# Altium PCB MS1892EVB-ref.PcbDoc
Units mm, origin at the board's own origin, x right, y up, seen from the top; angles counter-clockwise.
Board outline 71.73 x 36.12 mm, 2 copper layers (Top Layer, Bottom Layer); 57 components, 56 nets, 213 pads, 111 vias.
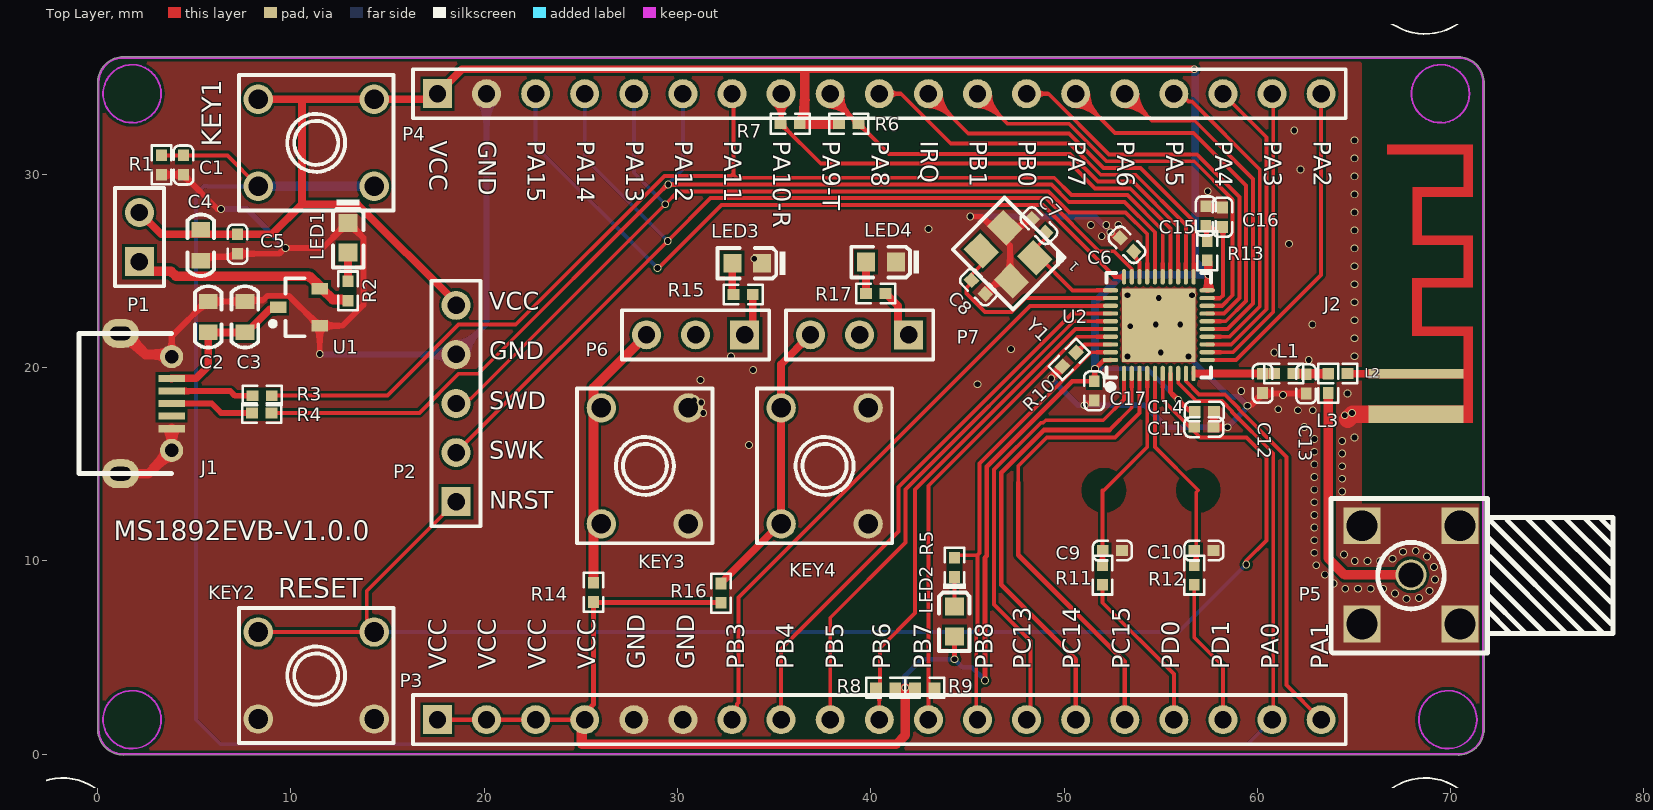
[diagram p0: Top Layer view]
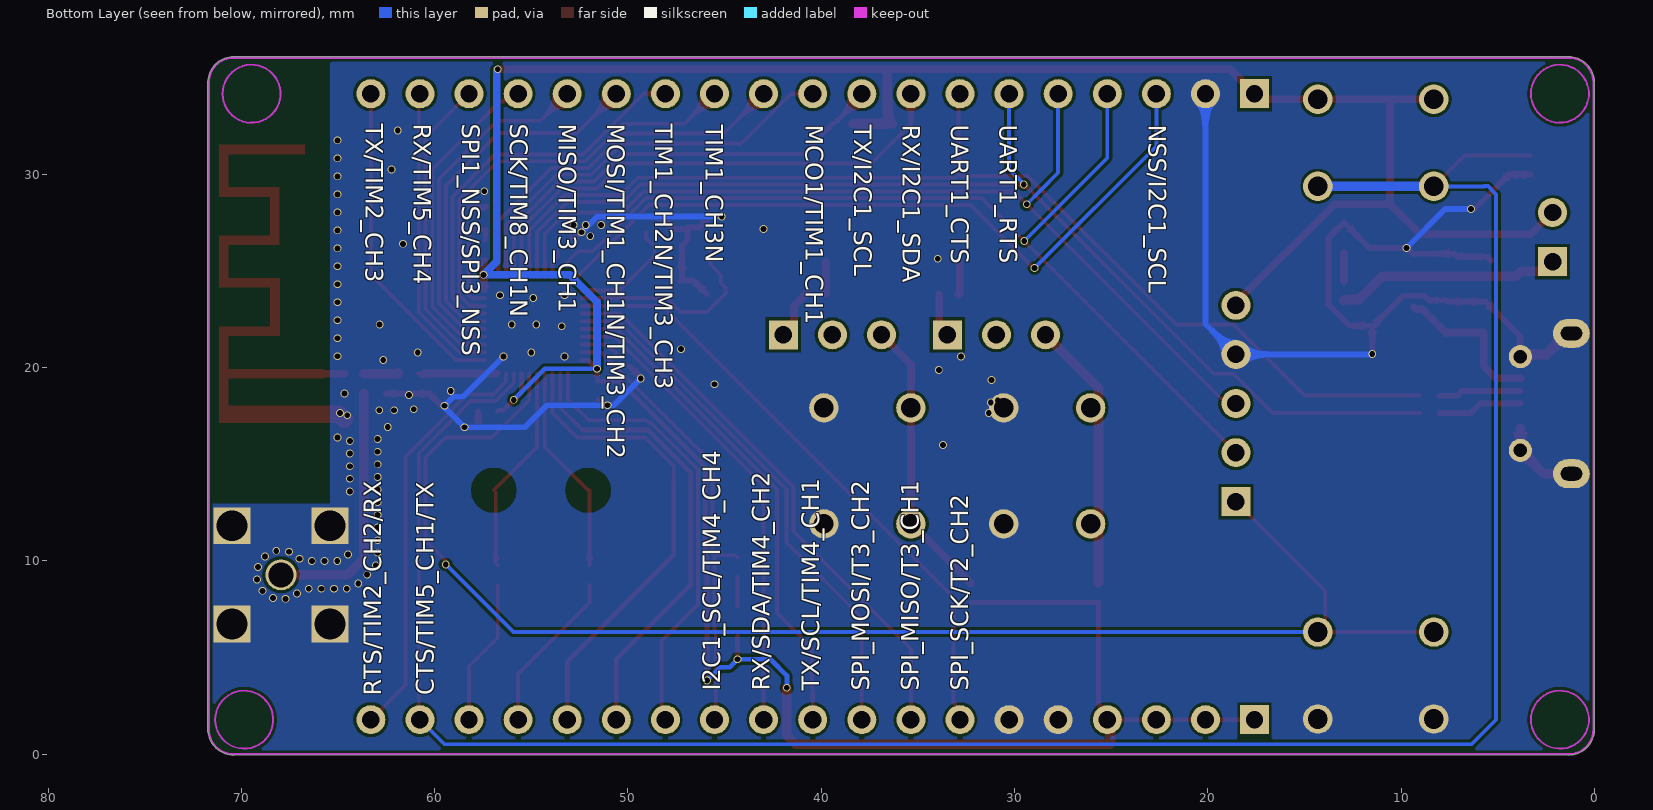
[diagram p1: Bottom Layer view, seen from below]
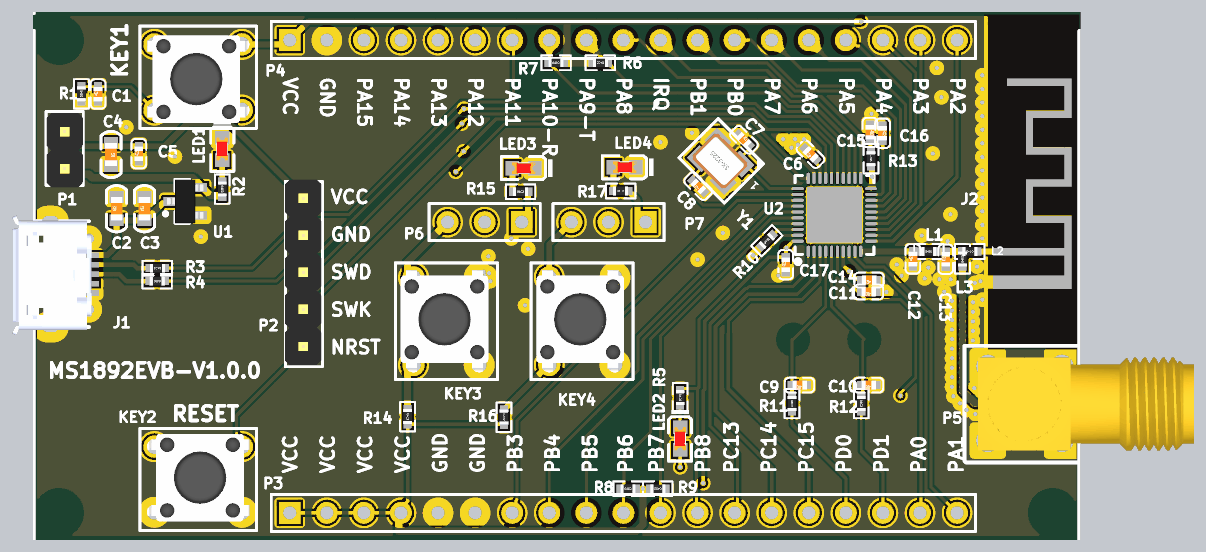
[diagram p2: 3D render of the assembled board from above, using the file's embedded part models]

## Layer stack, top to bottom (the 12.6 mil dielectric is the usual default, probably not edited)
Top Solder: solder mask 0.0102, Solder Resist, Dk 3.5
Top Layer: signal copper 0.0356
Dielectric 1: dielectric 0.32, FR-4, Dk 4.8
Bottom Layer: signal copper 0.0356
Bottom Solder: solder mask 0.0102, Solder Resist, Dk 3.5

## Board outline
-0.003,1.27 ccw(c1.317,1.27) 1.317,-0.05 ccw(c1.317,0) 1.317,-0.05 70.388,-0.048 ccw(c70.404,0) 70.404,-0.05 ccw(c70.404,1.27) 70.488,-0.048 ccw(c70.404,1.27) 71.715,1.114 ccw(c71.674,1.143) 71.724,1.143 71.724,34.798 ccw(c71.674,34.798) 71.723,34.809 ccw(c70.404,34.752) 70.404,36.072 1.317,36.071 ccw(c1.317,34.751) -0.002,34.809 ccw(c0.047,34.798) -0.003,34.798

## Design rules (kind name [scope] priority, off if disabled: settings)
Clearance [All] p1: gap=0.15
ComponentClearance [All] p1 off: gap=0.254 collisioncheckmode=3 verticalgap=0.254 showdistances=FALSE
Height [All] p1: minheight=0 maxheight=50 prefheight=12.7
HoleToHoleClearance [All] p1: gap=0 allowstackedmicrovias=FALSE
MinimumSolderMaskSliver [All] p1 off: minsoldermaskwidth=0
PlaneConnect [All] p1: planeconnectstyle=Direct reliefexpansion=0.508 reliefentries=4 reliefconductorwidth=0.254 reliefairgap=0.254
PolygonConnect PolygonConnect_29 [All vs IsNamedPolygon('GND_L02_P012')] p1: connectstyle=Direct reliefconductorwidth=0.254 reliefentries=4 polygonreliefangle="90 Angle" airgapwidth=0.254
PolygonConnect PolygonConnect_28 [All vs IsNamedPolygon('GND_L01_P010')] p2: connectstyle=Direct reliefconductorwidth=0.254 reliefentries=4 polygonreliefangle="90 Angle" airgapwidth=0.254
PolygonConnect PolygonConnect_27 [All vs IsNamedPolygon('Top Layer-No Net')] p3: connectstyle=Direct reliefconductorwidth=0.254 reliefentries=4 polygonreliefangle="90 Angle" airgapwidth=0.254
PolygonConnect PolygonConnect_26 [All vs IsNamedPolygon('Top Layer-No Net')] p4: connectstyle=Direct reliefconductorwidth=0.254 reliefentries=4 polygonreliefangle="90 Angle" airgapwidth=0.254
PolygonConnect PolygonConnect_25 [All vs IsNamedPolygon('GND_L02_P026')] p5: connectstyle=Direct reliefconductorwidth=0.254 reliefentries=4 polygonreliefangle="90 Angle" airgapwidth=0.254
PolygonConnect PolygonConnect_24 [All vs IsNamedPolygon('GND_L01_P028')] p6: connectstyle=Direct reliefconductorwidth=0.254 reliefentries=4 polygonreliefangle="90 Angle" airgapwidth=0.254
PolygonConnect PolygonConnect_23 [All vs IsNamedPolygon('GND_L02_P022')] p7: connectstyle=Direct reliefconductorwidth=0.254 reliefentries=4 polygonreliefangle="90 Angle" airgapwidth=0.254
PolygonConnect PolygonConnect_22 [All vs IsNamedPolygon('GND_L01_P020')] p8: connectstyle=Direct reliefconductorwidth=0.254 reliefentries=4 polygonreliefangle="90 Angle" airgapwidth=0.254
PolygonConnect PolygonConnect_21 [All vs IsNamedPolygon('GND_L02_P016')] p9: connectstyle=Direct reliefconductorwidth=0.254 reliefentries=4 polygonreliefangle="90 Angle" airgapwidth=0.254
PolygonConnect PolygonConnect_20 [All vs IsNamedPolygon('GND_L01_P018')] p10: connectstyle=Direct reliefconductorwidth=0.254 reliefentries=4 polygonreliefangle="90 Angle" airgapwidth=0.254
PolygonConnect PolygonConnect_19 [All vs IsNamedPolygon('GND_L02_P014')] p11: connectstyle=Direct reliefconductorwidth=0.254 reliefentries=4 polygonreliefangle="90 Angle" airgapwidth=0.254
PolygonConnect PolygonConnect_18 [All vs IsNamedPolygon('GND_L02_P012')] p12: connectstyle=Direct reliefconductorwidth=0.254 reliefentries=4 polygonreliefangle="90 Angle" airgapwidth=0.254
PolygonConnect PolygonConnect_17 [All vs IsNamedPolygon('GND_L02_P010')] p13: connectstyle=Direct reliefconductorwidth=0.254 reliefentries=4 polygonreliefangle="90 Angle" airgapwidth=0.254
PolygonConnect PolygonConnect_16 [All vs IsNamedPolygon('GND_L01_P008')] p14: connectstyle=Direct reliefconductorwidth=0.254 reliefentries=4 polygonreliefangle="90 Angle" airgapwidth=0.254
PolygonConnect PolygonConnect_15 [All vs IsNamedPolygon('GND_L02_P010')] p15: connectstyle=Relief reliefconductorwidth=0.254 reliefentries=4 polygonreliefangle="45 Angle" airgapwidth=0.254
PolygonConnect PolygonConnect_14 [All vs IsNamedPolygon('GND_L01_P008')] p16: connectstyle=Relief reliefconductorwidth=0.254 reliefentries=4 polygonreliefangle="45 Angle" airgapwidth=0.254
PolygonConnect PolygonConnect_13 [All vs IsNamedPolygon('GND_L02_P010')] p17: connectstyle=Relief reliefconductorwidth=0.254 reliefentries=4 polygonreliefangle="45 Angle" airgapwidth=0.254
PolygonConnect PolygonConnect_12 [All vs IsNamedPolygon('GND_L01_P008')] p18: connectstyle=Relief reliefconductorwidth=0.254 reliefentries=4 polygonreliefangle="45 Angle" airgapwidth=0.254
PolygonConnect PolygonConnect_11 [All vs IsNamedPolygon('GND_L02_P006')] p19: connectstyle=Direct reliefconductorwidth=0.254 reliefentries=4 polygonreliefangle="90 Angle" airgapwidth=0.254
PolygonConnect PolygonConnect_10 [All vs IsNamedPolygon('GND_L01_P004')] p20: connectstyle=Direct reliefconductorwidth=0.254 reliefentries=4 polygonreliefangle="90 Angle" airgapwidth=0.254
PolygonConnect PolygonConnect_9 [All vs IsNamedPolygon('GND_L01_P004')] p21: connectstyle=Relief reliefconductorwidth=0.254 reliefentries=4 polygonreliefangle="45 Angle" airgapwidth=0.254
PolygonConnect PolygonConnect_8 [All vs IsNamedPolygon('GND_L02_P006')] p22: connectstyle=Relief reliefconductorwidth=0.254 reliefentries=4 polygonreliefangle="45 Angle" airgapwidth=0.254
PolygonConnect PolygonConnect_7 [All vs IsNamedPolygon('GND_L01_P004')] p23: connectstyle=Relief reliefconductorwidth=0.254 reliefentries=4 polygonreliefangle="45 Angle" airgapwidth=0.254
PolygonConnect PolygonConnect_6 [All vs IsNamedPolygon('GND_L02_P006') Or  IsNamedPolygon('GND_L01_P004')] p24: connectstyle=Relief reliefconductorwidth=0.254 reliefentries=4 polygonreliefangle="45 Angle" airgapwidth=0.254
PolygonConnect PolygonConnect_5 [All vs IsNamedPolygon('GND_L01_P000')] p25: connectstyle=Direct reliefconductorwidth=0.254 reliefentries=4 polygonreliefangle="90 Angle" airgapwidth=0.254
PolygonConnect PolygonConnect_4 [All vs IsNamedPolygon('GND_L02_P002')] p26: connectstyle=Direct reliefconductorwidth=0.254 reliefentries=4 polygonreliefangle="90 Angle" airgapwidth=0.254
PolygonConnect PolygonConnect_3 [All vs IsNamedPolygon('GND_L01_P002')] p27: connectstyle=Direct reliefconductorwidth=0.254 reliefentries=4 polygonreliefangle="90 Angle" airgapwidth=0.254
PolygonConnect PolygonConnect_2 [All vs IsNamedPolygon('GND_L02_P000')] p28: connectstyle=Direct reliefconductorwidth=0.254 reliefentries=4 polygonreliefangle="90 Angle" airgapwidth=0.254
PolygonConnect PolygonConnect_1 [All vs IsNamedPolygon('GND_L02_P000')] p29: connectstyle=Direct reliefconductorwidth=0.254 reliefentries=4 polygonreliefangle="90 Angle" airgapwidth=0.254
PolygonConnect [All] p30: connectstyle=Relief reliefconductorwidth=0.254 reliefentries=4 polygonreliefangle="90 Angle" airgapwidth=0.254
RoutingVias [All] p1: holewidth=0.3 width=0.4 viastyle="Through Hole" minholewidth=0.3 minwidth=0.4 maxholewidth=0.711 maxwidth=1.27
SilkToSilkClearance [All] p1 off: silktosilkclearance=0
SilkToSolderMaskClearance [IsPad] p1 off: minsilkscreentomaskgap=0 clearancetoexposedcopper=TRUE
SolderMaskExpansion [All] p1: expansion=0.3
Width [All] p1: maxlimit=1 minlimit=0.1 preferedwidth=0.2
22 further rules are at their usual default settings.

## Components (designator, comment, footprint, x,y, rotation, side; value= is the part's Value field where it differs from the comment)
C1 "0.1uF" C0402 4.445,30.977 r90 top
C2 "47uF" c0603 5.715,22.614 r90 top
C3 "0.1uF" c0603 7.62,22.614 r90 top
C4 "1uF" C0603 5.334,26.327 r270 top
C5 "0.1uF" C0402 7.239,26.888 r90 top
C6 "10uF" C0402 52.899,26.707 r135 top
C7 "15pF" C0402 49.046,26.979 r315 top
C8 "15pF" C0402 45.212,24.511 r135 top
C9 "15pF" C0402 51.999,10.528 r180 top
C10 "15pF" C0402 56.731,10.528 r180 top
C11 "0.1uF" C0402 56.731,16.913 r180 top
C12 "NC" C0402 60.27,19.674 r90 top
C13 "NC" C0402 62.522,19.651 r90 top
C14 "10uF" C0402 56.757,17.729 r180 top
C15 "1uF" C0402 57.324,27.337 r270 top
C16 "0.1uF" C0402 58.188,27.273 r270 top
C17 "0.01uF" C0402 51.557,19.287 r90 top
J1 "USB-Micro" USB-MICRO 3.823,18.135 r90 top
J2 "ANTENNA--F" ANT-2 68.199,19.682 r90 top
KEY1 "Button" SW_DIP 11.303,31.623 r90 top
KEY2 "Button" SW_DIP 11.303,4.064 r270 top
KEY3 "Button" SW_DIP 28.307,14.908 r0 top
KEY4 "Button" SW_DIP 37.607,14.908 r0 top
L1 "0R" R0402 61.871,19.682 r0 top
L2 "0R" R0402 63.665,19.682 r180 top
L3 "0R" R0402 63.665,19.674 r90 top
LED1 "LED2" LED_0603 12.954,26.709 r270 top
LED2 "LED2" LED_0603 44.323,6.858 r270 top
LED3 "LED2" LED_0603 33.603,25.392 r180 top
LED4 "LED2" LED_0603 40.521,25.453 r180 top
P1 "Header 2" HDR1X2 2.159,25.476 r90 top
P2 "SWD" HDR1X5 18.542,13.055 r90 top
P3 "Header 19" HDR1X19 17.577,1.778 r0 top
P4 "Header 19" HDR1X19 17.577,34.163 r0 top
P5 "SMA_FLAT" SMA-KWE 65.405,6.731 r0 top
P6 "Header 3" HDR1X3 33.472,21.691 r180 top
P7 "Header 3" HDR1X3 41.956,21.691 r180 top
R1 "4.7K" R0402 3.302,29.977 r270 top
R2 "2K" R0402 12.954,23.458 r270 top
R3 "22R" R0402 8.001,18.542 r180 top
R4 "22R" R0402 7.988,17.653 r180 top
R5 "2K" R0402 44.323,9.16 r270 top
R6 "4.7K" R0402 38.354,32.608 r180 top
R7 "4.7K" R0402 36.322,32.608 r0 top
R8 "4.7K" R0402 41.259,3.429 r0 top
R9 "4.7K" R0402 42.291,3.429 r180 top
R10 "4.7K" R0402 50.618,20.773 r45 top
R11 "0R" R0402 51.987,8.763 r270 top
R12 "0R" R0402 56.731,8.763 r270 top
R13 "0R" R0402 57.403,26.543 r90 top
R14 "4.7K" R0402 25.651,7.866 r270 top
R15 "2K" R0402 33.892,23.777 r0 top
R16 "4.7K" R0402 32.254,7.83 r270 top
R17 "2K" R0402 40.751,23.829 r0 top
U1 "AP7333-SA-2.8V" SOT23_L 10.414,23.114 r180 top
U2 "MS1892" QFN-40_5x5x04P 54.899,22.19 r0 top
Y1 "16MHz 12pF 20ppm" XT3225 49.114,25.611 r135 top

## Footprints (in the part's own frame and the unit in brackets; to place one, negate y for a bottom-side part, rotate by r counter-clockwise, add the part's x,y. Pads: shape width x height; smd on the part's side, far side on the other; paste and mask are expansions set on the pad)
ANT-2 [mm]
  rect 0.5x4.9 smd: 1(0,0)
  rect 0.9x4.9 smd: 2(-2.1,0)
  Top Layer region: -0.25,-2.45 0.25,-2.45 0.25,2.45 -0.25,2.45
  Top Layer region: 11.35,-2.45 11.85,-2.45 11.85,1.49 11.35,1.49
  Top Layer region: 9.15,-2.95 11.85,-2.95 11.85,-2.45 9.15,-2.45
  Top Layer region: 9.15,-2.452 9.65,-2.452 9.65,0.188 9.15,0.188
  Top Layer region: 7.15,-0.312 9.15,-0.312 9.15,0.188 7.15,0.188
  Top Layer region: 6.65,-2.452 7.15,-2.452 7.15,0.188 6.65,0.188
  Top Layer region: 4.45,-2.95 7.15,-2.95 7.15,-2.45 4.45,-2.45
  Top Layer region: 4.45,-2.45 4.95,-2.45 4.95,0.19 4.45,0.19
  Top Layer region: 2.45,-0.31 4.45,-0.31 4.45,0.19 2.45,0.19
  Top Layer region: 1.95,-2.45 2.45,-2.45 2.45,0.19 1.95,0.19
  Top Layer region: -2.55,-2.95 2.45,-2.95 2.45,-2.45 -2.55,-2.45
  Top Layer region: -2.548,-2.45 -1.648,-2.45 -1.648,2.45 -2.548,2.45
C0402 [mil]
  rect 24x22 smd: 1(0,0) 2(-39.37,0)
  silkscreen extent -59,-20 20,20, body extent -40,-12 0,12, height 8
c0603 [mm]
  rect 0.8x0.965 smd: 1(-0.8,0) 2(0.8,0)
  silkscreen extent -1.59,-0.69 1.59,0.69, body extent -0.8,-0.4 0.8,0.4, height 0.3
C0603 [mm]
  rect 0.8x0.965 smd: 1(-0.8,0) 2(0.8,0)
  silkscreen extent -1.59,-0.69 1.59,0.69, body extent -0.8,-0.4 0.8,0.4, height 0.3
HDR1X2 [mm] "Connector; Header; 2 Position"
  rect 1.5x1.5 hole 0.9: 1(0,0)
  round 1.5 hole 0.9: 2(2.54,0)
  silkscreen extent -1.27,-1.27 3.81,1.27, body extent -1.4,-1.24 3.68,1.24, height 8.54
HDR1X3 [mm] "Connector; Header; 3 Position"
  rect 1.5x1.5 hole 0.9: 1(0,0)
  round 1.5 hole 0.9: 2(2.54,0) 3(5.08,0)
  silkscreen extent -1.27,-1.27 6.35,1.27
HDR1X5 [mm] "Connector; Header; 5 Position"
  rect 1.5x1.5 hole 0.9: 1(0,0)
  round 1.5 hole 0.9: 2(2.54,0) 3(5.08,0) 4(7.62,0) 5(10.16,0)
  silkscreen extent -1.27,-1.27 11.43,1.27, body extent -1.15,-1.2 11.55,1.29, height 8.54
HDR1X19 [mm] "Connector; Header; 19 Position"
  rect 1.5x1.5 hole 0.9: 1(0,0)
  round 1.5 hole 0.9: 2(2.54,0) 3(5.08,0) 4(7.62,0) 5(10.16,0) 6(12.7,0) 7(15.24,0) 8(17.78,0) 9(20.32,0) 10(22.86,0) 11(25.4,0) 12(27.94,0) 13(30.48,0) 14(33.02,0) 15(35.56,0) 16(38.1,0) 17(40.64,0) 18(43.18,0) 19(45.72,0)
  silkscreen extent -1.27,-1.27 46.99,1.27
LED_0603 [mm]
  rect 0.93x0.98 smd: 1(0.77,0) 2(-0.77,0)
  silkscreen extent -1.97,-0.79 1.54,0.79, body extent -0.8,-0.4 0.8,0.4, height 0.6
QFN-40_5x5x04P [mm]
  rect 3.8x3.8 smd mask+0.051: 0(0,0)
  oval 0.22x0.8 smd mask+0.051: 1(-1.8,-2.5) 2(-1.4,-2.5) 3(-1,-2.5) 4(-0.6,-2.5) 5(-0.2,-2.5) 6(0.2,-2.5) 7(0.6,-2.5) 8(1,-2.5) 9(1.4,-2.5) 10(1.8,-2.5) 21(1.8,2.5) 22(1.4,2.5) 23(1,2.5) 24(0.6,2.5) 25(0.2,2.5) 26(-0.2,2.5) 27(-0.6,2.5) 28(-1,2.5) 29(-1.4,2.5) 30(-1.8,2.5)
  oval 0.8x0.22 smd mask+0.051: 11(2.5,-1.8) 12(2.5,-1.4) 13(2.5,-1) 14(2.5,-0.6) 15(2.5,-0.2) 16(2.5,0.2) 17(2.5,0.6) 18(2.5,1) 19(2.5,1.4) 20(2.5,1.8) 31(-2.5,1.8) 32(-2.5,1.4) 33(-2.5,1) 34(-2.5,0.6) 35(-2.5,0.2) 36(-2.5,-0.2) 37(-2.5,-0.6) 38(-2.5,-1) 39(-2.5,-1.4) 40(-2.5,-1.8)
  silkscreen extent -2.7,-3.35 2.7,2.7
R0402 [mil]
  rect 24x22 smd: 1(0,0) 2(-39.37,0)
  silkscreen extent -59,-20 20,20, body extent -40,-12 0,12, height 13
SMA-KWE [mm]
  round 1.6 hole 1.3: 1(2.54,2.54)
  rect 1.9x1.9 hole 1.6: 2(0,0) 2(0,5.08) 2(5.08,0) 2(5.08,5.08)
  silkscreen extent -1.6,-1.5 13,6.5, body extent -0.67,-0.68 14.12,5.67, height 9.57
SOT23_L [mm]
  rect 0.85x0.6 smd: 1(-1.075,0.95) 2(-1.075,-0.95) 3(1.075,0)
  silkscreen extent -0.3,-1.5 1.47,1.5, body extent -1.25,-1.5 1.25,1.5, height 1.05
SW_DIP [mil]
  round 60 hole 40: 1(88.58,118.11) 2(88.58,-118.11) 3(-88.58,-118.11) 4(-88.58,118.11)
  silkscreen extent -138,-157 138,157, body extent -123,-157 113,167, height 291
USB-MICRO [mil]
  oval 59.06x74.8 hole 27.56 slot 43.31 at 90 deg: 0(-143,104) 0(143,104)
  round 47.24 hole 27.5: 0(-95.5,0) 0(95.5,0)
  rect 15x54 smd: 1(51,0) 2(25.5,0) 3(0,0) 4(-25.5,0) 5(-51,0)
  silkscreen extent -143,0 143,189, body extent -165,-7 158,207, height 97
XT3225 [mm]
  rect 1.4x1.2 smd: 1(0.5,0.4) 2(2.7,0.4) 3(2.7,2.1) 4(0.5,2.1)
  silkscreen extent -0.6,-0.7 3.8,3.1, body extent -0.1,-0.1 3.3,2.6, height 0.81

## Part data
C1 C2 C3 C4 C5 C6 C7 C8 C9 C10 C11 C12 C13 C14 C15 C16 C17: library part CAP, "Capacitor"
J2: library part ANT
KEY1 KEY2 KEY3 KEY4: library part KEY-4
L1 L2 L3: library part Res2, "Resistor"
LED1 LED2 LED3 LED4: "Typical RED, GREEN, YELLOW, AMBER GaAs LED"
P1: "Header, 2-Pin"
P2: library part "Header 5", "Header, 5-Pin"
P3 P4: "Header, 19-Pin"
P6 P7: "Header, 3-Pin"
R1 R2 R3 R4 R5 R6 R7 R8 R9 R10 R11 R12 R13 R14 R15 R16 R17: library part R
U1: library part SGM2300
U2: "M3+MG126"
Y1: library part XTAL3225

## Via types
v1: diameter 0.4, hole 0.3, Top Layer to Bottom Layer, 111 vias

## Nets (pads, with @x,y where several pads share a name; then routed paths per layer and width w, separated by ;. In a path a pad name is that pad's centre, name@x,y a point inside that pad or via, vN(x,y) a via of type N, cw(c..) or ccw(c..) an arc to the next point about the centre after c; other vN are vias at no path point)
DM-PA11: P4.7 R3.2 U2.25 | length 58.5
  Top Layer w0.2: R3.2 14.995,18.542 18.668,22.215 21.628,22.215 29.326,29.914 32.759,29.914 32.817,29.972 ; P4.7 32.895,34.085 32.895,29.97 33.051,29.814 49.488,29.814 50.383,28.919 53.273,28.919 55.099,27.093 U2.25@55.099,24.774
DP-PA12: P4.6 R4.2 U2.26 | length 58.9
  Top Layer w0.2: R4.2 16.646,17.653 18.668,19.675 19.685,19.675 29.474,29.464 v1(29.513,29.464) 49.343,29.464 50.238,28.569 53.128,28.569 54.699,26.998 U2.26
  Bottom Layer w0.2: v1(29.513,29.464) 29.513,29.503 30.277,30.267 P4.6
GND: C1.2 C2.2 C3.2 C4.2 C5.2 C6.1 C7.2 C8.2 C9.2 C10.2 C11.2 C12.2 C13.2 C14.2 C15.2 C16.2 C17.2 J1.0 J1.5 J2.2 KEY2.1 KEY2.2 KEY3.1 KEY3.2 KEY4.1 KEY4.2 LED1.2 LED3.2 LED4.2 P2.4 P3.5 P3.6 P4.2 P5.2 R1.1 R10.2 U1.1 U2.0 Y1.2 Y1.4 | length 106.8
  Top Layer w0.3: R1.1 C1.2 4.445,29.952 6.203,28.194 v1(6.382,28.194) ; J1.0@3.823,20.561 3.829,20.567 3.829,21.611 5.633,23.414 C3.2 7.683,23.477 8.553,23.477 8.79,23.714 9.888,23.714 11.214,22.388 11.214,22.314 11.364,22.164 U1.1 ; C4.2 5.54,25.733 C5.2@7.11,25.733 ; C5.2 9.387,25.888 9.687,26.188 11.638,26.188 12.929,27.479 12.979,27.479 13.744,26.714 13.744,23.24 12.668,22.164 U1.1 ; v1(11.489,20.701) U1.1 ; v1(45.14,27.813) 45.159,27.794 45.729,27.794 46.286,27.237 Y1.2 ; C8.2 46.617,24.502 Y1.4@47.253,24.502 ; Y1.4 Y1.4@47.253,24.502 ; C7.2 48.335,27.69 48.152,27.69 47.629,27.166 46.993,27.166 Y1.2 ; v1(49.33,19.432) 49.33,19.485 R10.2 ; v1(51.057,18.043) 51.084,18.043 51.172,18.132 51.428,18.132 51.529,18.233 51.529,18.258 C17.2 ; v1(52.399,26.998) 52.425,26.998 52.716,26.707 C6.1 ; C15.2 57.388,28.273 C16.2 ; C14.2 57.744,17.716 57.744,16.926 C11.2 v1(58.454,16.913) ; v1@59.664,18.043 60.27,18.649 C12.2 60.293,18.651 C13.2 ; Y1.2 46.922,26.601 47.205,26.318 47.205,24.55 Y1.4@47.253,24.502
  Top Layer w0.5: J1.0@1.182,14.503 2.617,14.503 3.823,15.709 J1.5 ; J1.0@1.182,21.767 1.382,21.767 2.473,20.676 3.708,20.676 J1.0@3.823,20.561
  Top Layer w0.9: 64.665,17.317 64.929,17.582 J2.2
  Bottom Layer w0.3: v1(6.382,28.194) 7.708,28.194 v1(9.714,26.188) ; v1(11.489,20.701) 11.515,20.675 P2.4 20.117,22.25 P4.2 ; v1(45.14,27.813) 51.584,27.813 v1(52.399,26.998) ; v1(49.33,19.432) 50.719,18.043 v1(51.057,18.043) 54.19,18.043 55.32,16.913 v1(58.454,16.913) 59.468,17.927 59.468,18.005 v1(59.487,18.024) 59.027,18.484 58.53,18.484 v1(56.44,20.574)
  other v1: 67.708,8.028 68.36,8.076 67.119,8.313 68.902,8.443 64.549,8.553 65.203,8.553 65.857,8.553 66.511,8.553 63.952,8.82 69.187,9.031 63.489,9.282 69.141,9.684 63.047,9.764 65.04,9.989 65.694,9.989 66.348,9.989 66.992,10.104 68.775,10.226 64.478,10.324 62.947,10.41 67.535,10.468 68.187,10.513 62.947,11.064 62.947,11.718 62.947,12.372 62.947,13.026 64.382,13.587 62.947,13.68 64.382,14.241 62.947,14.334 64.382,14.895 62.947,14.988 64.382,15.549 62.947,15.642 33.694,15.994 64.382,16.203 62.947,16.296 65.024,16.383 62.42,16.926 64.516,17.527 31.328,17.65 64.897,17.65 62.092,17.784 62.863,17.784 61.072,17.838 31.221,18.191 30.861,18.288 61.325,18.577 64.665,18.649 59.165,18.789 45.517,19.129 31.185,19.349 33.909,19.868 62.655,20.39 32.759,20.574 53.273,20.574 65.024,20.577 54.999,20.773 60.871,20.773 47.253,20.95 65.024,21.508 53.418,22.132 54.737,22.225 56.007,22.225 62.843,22.225 65.024,22.44 65.024,23.371 54.899,23.594 53.273,23.739 56.612,23.733 65.024,24.302 65.024,25.233 33.966,25.629 65.024,26.164 61.634,26.396 51.946,26.795 65.024,27.095 42.977,27.166 51.383,27.378 52.182,27.378 52.806,27.378 65.024,28.026 65.024,28.957 57.431,29.114 65.024,29.888 62.23,30.246 65.024,30.819 65.024,31.75 61.909,32.258
IRQ: P4.11 U2.21 | length 19.3
  Top Layer w0.2: P4.11 45.04,32.1 50.256,32.1 52.037,30.319 53.956,30.319 56.699,27.576 U2.21
NetC6_2: C6.2 U2.28 | length 1.4
  Top Layer w0.2: C6.2 53.606,25.746 53.899,25.453 U2.28
NetC7_1: C7.1 U2.31 Y1.1 | length 5.9
  Top Layer w0.2: C7.1 49.064,26.961 49.064,26.707 48.612,26.255 48.612,25.81 50.432,23.99 U2.31
NetC8_1: C8.1 U2.32 Y1.3 | length 10.7
  Top Layer w0.2: Y1.3 45.73,26.025 45.73,25.318 45.194,24.783 45.194,24.378 44.94,24.124 44.94,23.833 45.904,22.869 47.276,22.869 47.997,23.59 U2.32
NetC12_1: C12.1 L1.2 U2.10 | length 4.6
  Top Layer w0.2: U2.10@56.708,19.749 56.699,19.74 U2.10 56.835,19.69 ; C12.1@60.518,19.674 L1.2@60.811,19.674 ; L1.2@60.569,19.622 60.811,19.622 L1.2
  Top Layer w0.4: 56.835,19.69 60.502,19.69 60.518,19.674 L1.2@60.569,19.622
NetC13_1: C13.1 L1.1 L2.1 L3.1 | length 1.9
  Top Layer w0.5: L1.1@61.909,19.72 ccw(c61.909,19.682) L1.1 62.522,19.682 L2.1
NetJ1_2: J1.2 R3.1 | length 4.3
  Top Layer w0.3: J1.2@3.83,18.776 J1.2 6.855,18.783 7.096,18.542 R3.1
NetJ1_3: J1.3 R4.1 | length 4.4
  Top Layer w0.3: J1.3 5.9,18.135 6.382,17.653 R4.1
NetJ2_1: J2.1 L2.2 | length 3.5
  Top Layer w0.4: L2.2 J2.1
NetKEY3_3: KEY3.3 KEY3.4 P6.3 R14.2 | length 14
  Top Layer w0.5: R14.2 25.651,18.95 P6.3
NetKEY4_3: KEY4.3 KEY4.4 P7.3 R16.2 | length 14.8
  Top Layer w0.25: KEY4.3@35.306,11.908 KEY4.3
  Top Layer w0.4: R16.2 32.254,8.855 KEY4.3@35.306,11.908 ; KEY4.3 KEY4.4 35.357,20.173 P7.3
NetL3_2: L3.2 P5.1 | length 13.2
  Top Layer w0.5: L3.2 63.665,10.122 64.516,9.271 P5.1
NetLED1_1: LED1.1 R2.2 | length 1.5
  Top Layer w0.4: R2.2 LED1.1
NetLED2_2: LED2.2 R5.1 | length 1.5
  Top Layer w0.2: LED2.2 R5.1
NetLED3_1: LED3.1 R15.2 | length 1.6
  Top Layer w0.4: LED3.1 32.833,23.836 R15.2
NetLED4_1: LED4.1 R17.2 | length 1.6
  Top Layer w0.4: R17.2 LED4.1
NetP6_1: P6.1 R15.1 | length 2.3
  Top Layer w0.4: P6.1 33.892,22.112 R15.1
NetP7_1: P7.1 R17.1 | length 2.7
  Top Layer w0.4: R17.1 40.776,23.829 41.406,23.199 41.406,22.241 P7.1
NetR10_1: R10.1 U2.38 | length 2
  Top Layer w0.2: R10.1 50.64,20.773 51.057,21.19 U2.38
NRST: C11.1 KEY2.3 KEY2.4 P2.1 U2.6 | length 75.5
  Top Layer w0.2: KEY2.3@7.922,6.314 13.922,6.314 13.922,8.435 P2.1 ; U2.6 55.099,18.325 57.041,16.383 59.435,16.383 60.468,15.35 60.468,11.052 59.418,10.002 v1(59.418,9.808)
  Bottom Layer w0.2: KEY2.4@13.922,6.314 55.923,6.314 v1(59.418,9.808)
PA0: C1.1 KEY1.3 KEY1.4 P3.18 R1.2 U2.8 | length 119.7
  Top Layer w0.2: R1.2 3.31,30.969 6.707,30.969 KEY1.4 ; U2.8 55.903,19.686 55.903,19.192 56.837,18.258 58.166,18.258 58.687,17.737 58.687,17.693 60.818,15.562 60.818,1.839 P3.18
  Bottom Layer w0.2: KEY1.4 5.679,29.373 5.671,29.381 5.505,29.381 5.081,28.957 5.081,1.778 6.351,0.508 59.487,0.508 P3.18
  Bottom Layer w0.5: KEY1.4 KEY1.3
PA1: P3.19 U2.9 | length 21.6
  Top Layer w0.2: U2.9 56.303,19.686 56.303,19.287 56.981,18.608 58.311,18.608 59.037,17.882 59.037,17.838 61.51,15.365 61.51,3.565 P3.19
PA2: P4.19 U2.11 | length 17.1
  Top Layer w0.2: U2.11 58.895,20.39 63.297,24.792 P4.19
PA3: P4.18 U2.12 | length 15.6
  Top Layer w0.2: U2.12 58.739,20.79 60.818,22.869 60.818,34.102 P4.18
PA4: P4.17 U2.13 | length 15.9
  Top Layer w0.2: U2.13 58.644,21.19 60.468,23.014 60.468,31.912 P4.17
PA5: P4.16 U2.14 | length 16.2
  Top Layer w0.2: P4.16@55.899,33.941 56.251,33.941 56.44,33.752 56.612,33.752 60.118,30.246 60.118,23.159 58.549,21.59 U2.14
PA6: P4.15 U2.15 | length 17.8
  Top Layer w0.2: P4.15 54.534,32.766 56.757,32.766 59.768,29.756 59.768,23.304 58.454,21.99 U2.15
PA7: P4.14 U2.16 | length 19.2
  Top Layer w0.2: P4.14 52.629,32.131 56.699,32.131 59.418,29.412 59.418,23.449 58.359,22.39 U2.16
PA8: P4.10 U2.22 | length 21.4
  Top Layer w0.2: P4.10 41.563,34.163 44.134,31.592 50.269,31.592 51.892,29.969 53.708,29.969 56.299,27.378 U2.22
PA9-TX: P4.9 R6.2 U2.23 | length 23.6
  Top Layer w0.2: P4.9 37.897,34.04 39.292,32.644 39.416,32.644 39.416,32.572 40.934,31.053 50.313,31.053 51.747,29.619 53.563,29.619 55.899,27.283 U2.23
PA10-RX: P4.8 R7.2 U2.24 | length 26.4
  Top Layer w0.2: P4.8 35.357,32.598 37.41,30.545 50.326,30.545 51.602,29.269 53.418,29.269 55.499,27.188 U2.24
PA13-SWDIO: P2.3 P4.5 U2.27 | length 49.7
  Top Layer w0.2: P2.3@19.05,18.135 19.05,18.291 19.143,18.384 19.299,18.384 v1(29.363,28.448) 30.029,29.114 49.198,29.114 50.284,28.028 53.174,28.028 54.299,26.903 U2.27
  Bottom Layer w0.2: P2.3 P2.3@18.542,18.399 ; P4.5 27.737,30.074 28.655,29.156 v1(29.363,28.448)
PA14-SWCLK: P2.2 P4.4 U2.29 | length 51.7
  Top Layer w0.2: P2.2 v1(29.49,26.543) 31.711,28.764 49.053,28.764 51.804,26.014 52.574,26.014 53.495,25.093 53.495,24.694 U2.29
  Bottom Layer w0.2: P4.4 25.197,30.836 v1(29.49,26.543)
PA15: P4.3 U2.30 | length 38.7
  Top Layer w0.2: v1(28.956,25.146) 29.009,25.146 32.277,28.414 48.908,28.414 52.632,24.69 U2.30
  Bottom Layer w0.2: P4.3 22.657,31.445 v1(28.956,25.146)
PB0: P4.13 U2.17 | length 20.5
  Top Layer w0.2: P4.13 49.183,34.163 52.327,31.019 56.875,31.019 59.068,28.826 59.068,23.594 58.264,22.79 U2.17
PB1: P4.12 U2.18 | length 22
  Top Layer w0.2: P4.12 47.072,32.608 50.243,32.608 52.182,30.669 56.73,30.669 58.718,28.682 58.718,23.739 58.169,23.19 U2.18
PB3: P3.7 U2.33 | length 32
  Top Layer w0.2: P3.7 33.066,2.027 33.066,2.586 33.147,2.667 33.147,8.093 48.24,23.186 52.395,23.186 U2.33
PB4: P3.8 U2.34 | length 29.2
  Top Layer w0.2: P3.8 35.357,5.439 41.437,11.518 41.437,13.825 50.401,22.79 U2.34
PB5: P3.9 U2.35 | length 27.7
  Top Layer w0.2: P3.9 37.897,7.053 41.787,10.943 41.787,13.68 50.496,22.39 U2.35
PB6: P3.10 R8.2 U2.36 | length 26.2
  Top Layer w0.2: P3.10 40.437,3.429 40.464,3.456 40.464,5.473 42.291,7.3 42.291,13.69 50.591,21.99 U2.36
PB7: P3.11 R9.2 U2.37 | length 24.7
  Top Layer w0.2: P3.11 42.977,13.881 50.686,21.59 U2.37
PB8: P3.12 R5.2 U2.39 | length 23.8
  Top Layer w0.2: R5.2 44.451,10.288 45.507,10.288 45.517,10.298 ; P3.12 45.454,1.841 45.454,6.307 45.517,6.37 45.517,10.298 ; U2.39 51.388,20.79 45.624,15.026 45.624,10.405 45.517,10.298
PC13: P3.13 U2.1 | length 23.4
  Top Layer w0.2: P3.13 48.26,1.981 48.26,5.842 46.374,7.728 46.374,14.716 48.797,17.139 48.915,17.139 49.048,17.272 52.022,17.272 53.099,18.349 U2.1
PC14: P3.14 U2.2 | length 24.3
  Top Layer w0.2: 52.346,16.764 53.499,17.917 U2.2
  Top Layer w0.25: P3.14 50.597,4.902 46.749,8.75 46.749,14.56 48.953,16.764 52.346,16.764
PC15: P3.15 U2.3 | length 24.9
  Top Layer w0.2: 47.625,14.043 47.625,14.906 49.102,16.383 52.632,16.383 53.899,17.65 U2.3
  Top Layer w0.25: 47.625,14.043 47.625,10.298 53.137,4.786 P3.15
PD0: C9.1 R11.2 U2.4 | length 10.9
  Top Layer w0.2: R11.2 51.987,13.648 ; 52.059,13.648 54.299,15.888 U2.4
PD0_IO: P3.16 R11.1 | length 8.5
  Top Layer w0.2: R11.1 51.987,7.83 55.677,4.14 P3.16
PD1: C10.1 R12.2 U2.5 | length 10.9
  Top Layer w0.2: U2.5 54.699,15.888 56.939,13.648 56.835,13.544 56.835,9.867 R12.2
PD1_IO: P3.17 R12.1 | length 7.6
  Top Layer w0.2: R12.1 56.731,6.032 58.217,4.546 P3.17
VBUS: C2.1 C3.1 J1.1 U1.3 | length 8.1
  Top Layer w0.4: J1.1 3.833,19.44 5.089,19.44 5.715,20.066 C2.1 C3.1 7.702,21.814 8.903,23.014 9.239,23.014 U1.3
VCC: C4.1 C5.1 C14.1 C17.1 KEY1.1 KEY1.2 LED2.1 P1.2 P2.5 P3.1 P3.2 P3.3 P3.4 P4.1 R6.1 R7.1 R8.1 R9.1 R13.2 R14.1 R16.1 U2.7 U2.20 U2.40 | length 176.9
  Top Layer w0.25: P3.1 P3.2 P3.3 P3.4@25.036,1.778 ; P3.4@25.036,1.617 P3.4@25.036,1.778 ; R16.1 32.236,7.848 25.669,7.848 R14.1 25.651,2.57 25.036,1.955 P3.4@25.036,1.778 ; v1(44.323,4.902) LED2.1 ; v1(45.904,3.81) 45.904,10.155 45.999,10.25 45.999,14.871 50.415,19.287 C17.1 51.58,19.309 51.58,19.911 v1(51.602,19.933) 52.044,20.375 52.384,20.375 U2.40 ; U2.7 55.499,18.725 v1(55.899,18.325) 56.44,17.784 56.702,17.784 C14.1 ; U2.20 57.456,23.99 U2.20@57.471,24.005 ; R13.2@57.403,25.518 R13.2
  Top Layer w0.4: P1.2 3.287,26.888 9.01,26.888 10.57,28.448 ; KEY1.1 10.57,33.873 ; P2.5 18.542,23.341 13.435,28.448 10.57,28.448 ; v1(56.73,35.433) 18.847,35.433 17.287,33.873 10.57,33.873 ; R13.2@57.403,25.518 57.471,25.449 v1(57.471,24.792) U2.20@57.471,24.08 ; 10.57,28.448 10.57,33.873
  Top Layer w0.5: P3.4@25.036,1.617 25.036,0.508 41.314,0.508 41.775,0.969 v1(41.775,3.429) ; R7.1 R7.1@36.347,32.608 ; R7.1@36.576,32.725 36.576,35.296 ; R7.1@36.576,32.862 36.377,32.663 36.377,32.637 R7.1@36.347,32.608 ; R6.1 R7.1@36.347,32.608
  Bottom Layer w0.25: v1(41.775,3.429) 41.775,4.056 42.621,4.902 v1(44.323,4.902) 44.73,4.495 45.219,4.495 v1(45.904,3.81) ; 51.892,19.933 54.291,19.933 v1(55.899,18.325)
  Bottom Layer w0.4: v1(51.602,19.933) 51.602,23.395 52.999,24.792 v1(57.471,24.792) 56.777,25.486 56.777,35.386 v1(56.73,35.433)
VCC_BLE: C15.1 C16.1 R13.1 U2.19 | length 5.9
  Top Layer w0.2: C15.1@57.325,27.146 C15.1@57.349,27.146 ; U2.19 58.074,23.59 58.217,23.733 58.217,27.244 C16.1 ; R13.1 57.364,26.582 57.364,27.132 C15.1@57.349,27.146 ; C16.1@58.162,27.146 C15.1@57.349,27.146
VCC_LED: P1.1 R2.1 U1.2 | length 11.6
  Top Layer w0.5: P1.1 2.659,24.976 3.801,24.976 4.05,24.727 10.951,24.727 11.614,24.064 12.165,23.513 12.925,23.513 12.954,23.483 R2.1
pads on no net: J1.4 P6.2 P7.2

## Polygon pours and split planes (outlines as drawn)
GND on Bottom Layer "GND_L02_P012" (solid, remove dead copper, pour order 12): 0.047,34.925 1.143,36.021 65.404,36.021 65.405,36.022 65.405,12.954 71.673,12.954 71.674,12.953 71.674,1.049 70.633,0.007 1.182,0.007 1.182,0.008 0.047,1.143
GND on Top Layer "GND_L01_P010" (solid, remove dead copper, pour order 10): 0.047,34.925 1.143,36.021 65.404,36.021 65.405,36.022 65.405,12.954 71.673,12.954 71.674,12.953 71.674,1.049 70.633,0.007 1.182,0.007 1.182,0.008 0.047,1.143

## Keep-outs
Keep-Out Layer:
  circle w0.1: c69.85,1.778 r1.5
  circle w0.1: c69.469,34.163 r1.5
  circle w0.1: c1.778,1.778 r1.5
  circle w0.1: c3.581,-12.065 r1.5
  circle w0.1: c1.778,34.163 r1.5
  lines w0.1: -17.225,5.207 ccw(c-15.955,5.207) -15.955,3.937 ; 0.047,34.798 0.047,1.27 ccw(c1.317,1.27) 1.317,0 70.485,0.003 ; 70.404,0 ccw(c70.404,1.27) 71.674,1.27 ; 71.674,1.143 71.674,34.798 ; 71.674,34.752 ccw(c70.404,34.752) 70.404,36.022 1.317,36.021 ; 1.317,36.021 ccw(c1.317,34.751) 0.047,34.751 cw(c1.317,34.751) 1.317,36.021
Mechanical 1:
  lines w0.1: 0.047,1.27 0.047,33.655 ; 71.674,1.397 71.673,34.798

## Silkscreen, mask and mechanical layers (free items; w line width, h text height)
Top Overlay:
  circle w0.1: c68.674,-4.239 r3
  circle w0.1: c68.674,40.259 r3
  circle w0.1: c-1.826,-4.239 r3
  circle w0.1: c3.581,-12.065 r3
  circle w0.1: c0.829,41.529 r3
  text "VCC" at 17.18,31.73 h0.9 r270
  text "GND" at 19.72,31.73 h0.9 r270
  text "PA15" at 22.26,31.73 h0.9 r270
  text "PA14" at 24.8,31.73 h0.9 r270
  text "PA13" at 27.34,31.73 h0.9 r270
  text "PA12" at 29.88,31.73 h0.9 r270
  text "PA11" at 32.42,31.73 h0.9 r270
  text "PA10-R" at 34.96,31.73 h0.9 r270
  text "PA9-T" at 37.5,31.73 h0.9 r270
  text "PA8" at 40.041,31.73 h0.9 r270
  text "IRQ" at 42.581,31.73 h0.9 r270
  text "PB1" at 45.121,31.73 h0.9 r270
  text "PB0" at 47.661,31.73 h0.9 r270
  text "PA7" at 50.201,31.73 h0.9 r270
  text "PA6" at 52.741,31.73 h0.9 r270
  text "PA5" at 55.281,31.73 h0.9 r270
  text "PA4" at 57.821,31.73 h0.9 r270
  text "PA3" at 60.361,31.73 h0.9 r270
  text "PA2" at 62.901,31.73 h0.9 r270
  text "POWER" at -14.859,28.658 h1
  text "VCC" at 20.266,22.995 h0.9
  text "GND" at 20.266,20.421 h0.9
  text "SWD" at 20.266,17.847 h0.9
  text "SWK" at 20.266,15.274 h0.9
  text "NRST" at 20.266,12.7 h0.9
  text "MS1892EVB-V1.0.0" at 0.829,11.049 h1
  text "RESET" at 9.339,8.093 h1
  text "VCC" at 18.034,4.382 h0.9 r90
  text "VCC" at 20.603,4.382 h0.9 r90
  text "VCC" at 23.171,4.382 h0.9 r90
  text "VCC" at 25.739,4.382 h0.9 r90
  text "GND" at 28.307,4.382 h0.9 r90
  text "GND" at 30.875,4.382 h0.9 r90
  text "PB3" at 33.444,4.382 h0.9 r90
  text "PB4" at 36.012,4.382 h0.9 r90
  text "PB5" at 38.58,4.382 h0.9 r90
  text "PB6" at 41.013,4.382 h0.9 r90
  text "PB7" at 43.135,4.382 h0.9 r90
  text "PB8" at 46.312,4.382 h0.9 r90
  text "PC13" at 48.267,4.382 h0.9 r90
  text "PC14" at 50.833,4.382 h0.9 r90
  text "PC15" at 53.4,4.382 h0.9 r90
  text "PD0" at 55.966,4.382 h0.9 r90
  text "PD1" at 58.532,4.382 h0.9 r90
  text "PA0" at 61.098,4.382 h0.9 r90
  text "PA1" at 63.665,4.382 h0.9 r90
Bottom Overlay:
  text "TIM1_CH2N/TIM3_CH3" at 48.571,32.622 h0.9 r90
  text "MOSI/TIM1_CH1N/TIM3_CH2" at 51.071,32.622 h0.9 r90
  text "MISO/TIM3_CH1" at 53.572,32.622 h0.9 r90
  text "SCK/TIM8_CH1N" at 56.072,32.622 h0.9 r90
  text "SPI1_NSS/SPI3_NSS" at 58.572,32.622 h0.9 r90
  text "RX/TIM5_CH4" at 61.073,32.622 h0.9 r90
  text "TX/TIM2_CH3" at 63.573,32.622 h0.9 r90
  text "NSS/I2C1_SCL" at 23.041,32.567 h0.9 r90
  text "UART1_RTS" at 30.766,32.567 h0.9 r90
  text "UART1_CTS" at 33.273,32.567 h0.9 r90
  text "RX/I2C1_SDA" at 35.781,32.567 h0.9 r90
  text "TX/I2C1_SCL" at 38.288,32.567 h0.9 r90
  text "MCO1/TIM1_CH1" at 40.796,32.567 h0.9 r90
  text "TIM1_CH3N" at 45.975,32.567 h0.9 r90
  text "SPI_SCK/T2_CH2" at 32.383,3.273 h0.9 r270
  text "SPI_MISO/T3_CH1" at 34.952,3.273 h0.9 r270
  text "SPI_MOSI/T3_CH2" at 37.522,3.273 h0.9 r270
  text "TX/SCL/TIM4_CH1" at 40.091,3.273 h0.9 r270
  text "RX/SDA/TIM4_CH2" at 42.66,3.273 h0.9 r270
  text "I2C1_SCL/TIM4_CH4" at 45.23,3.273 h0.9 r270
  text "CTS/TIM5_CH1/TX" at 60.036,3.04 h0.9 r270
  text "RTS/TIM2_CH2/RX" at 62.755,3.027 h0.9 r270
Top Solder:
  rectangle: 65.141,13.026 71.674,35.927
Bottom Solder:
  rectangle: 65.141,13.026 71.674,35.927
Mechanical 1:
  circle w0.1: c69.85,1.778 r1.5
  circle w0.1: c69.469,34.163 r1.5
  circle w0.1: c1.778,1.778 r1.5
  circle w0.1: c3.581,-12.065 r1.5
  circle w0.1: c1.778,34.163 r1.5
  lines w0.1: -18.161,4.572 ccw(c-16.891,4.572) -16.891,3.302 ; 0.039,34.744 cw(c1.309,34.744) 1.309,36.014 ; 0.053,1.27 ccw(c1.323,1.27) 1.323,0 ; 1.309,36.021 70.408,36.021 ; 1.32,0.003 70.485,0.003 ; 70.404,0 ccw(c70.404,1.27) 71.674,1.27 71.673,34.798 ; 70.404,36.022 cw(c70.404,34.752) 71.674,34.752

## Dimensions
0.047,0 to 1.317,36.021 on Top Overlay
0.047,34.798 to 71.674,1.143 on Top Overlay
